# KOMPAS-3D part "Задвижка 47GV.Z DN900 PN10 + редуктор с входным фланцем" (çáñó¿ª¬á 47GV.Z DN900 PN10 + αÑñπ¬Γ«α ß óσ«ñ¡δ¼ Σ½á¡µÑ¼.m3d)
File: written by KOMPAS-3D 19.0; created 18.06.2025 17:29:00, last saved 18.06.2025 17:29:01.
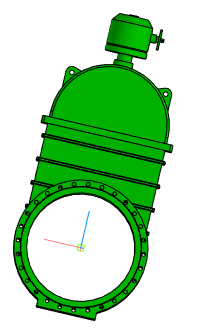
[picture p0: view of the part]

Document properties: Полное имя файла: Задвижка 47GV.Z DN900 PN10 + редуктор с входным валом.a3d

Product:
- Part/product: Задвижка 47GV.Z DN900 PN10 + редуктор с входным фланцем
    Масса: 3514.58
  - Body: Тело 1
      Масса: 3516.77

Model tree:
1. Операция без истории:1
